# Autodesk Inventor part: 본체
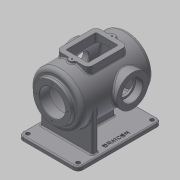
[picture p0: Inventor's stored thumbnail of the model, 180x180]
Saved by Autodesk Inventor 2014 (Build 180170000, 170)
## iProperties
Created: 2016-02
Part Number: 본체
Material: 일반
Document SubType Name: Modeling
Designer: mduedu
Density: 2.71 g/cm^3
Appearance: 기본값
Author: mduedu
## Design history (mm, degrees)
sketch "스케치2"
  geometry: L1 (0, 90)-(0, -90); L2 (65, -90)-(65, 90); L3 (65, 90)-(0, 90); L4 (65, -90)-(0, -90); 2 further points
  constraints: 8 end point, 2 horizontal, 1 coincident, 1 midpoint, 1 parallel, 1 vertical
  dimensions: "d3" = 180 distance of L1.start L1.end; "d5" = 130 diameter of L2 L1
revolve "회전1" sketch "스케치2" stored, may be unused: angle "d7" = 90 deg
sketch "스케치3"
  geometry: C1 r 47.5 at (0, 0); 1 further point
  constraints: 1 centre point, 1 coincident
  dimensions: "d8" = 95 diameter of C1
extrude "돌출2" join sketch "스케치3" distance "d10" = 10; taper "d11" = 0 deg
sketch "스케치5"
  geometry: L1 (47.5, 100)-(47.5, 90) reference; L2 (47.5, 90)-(65, 90) reference; L3 (65, 90)-(65, -90) reference; L4 (-65, -90)-(-65, 90) reference; L5 (-65, 90)-(-47.5, 90) reference; L6 (-47.5, 90)-(-47.5, 100) reference; L7 (-47.5, 100)-(47.5, 100) reference; L8 (55, 75)-(55, -75); L9 (0, 75)-(55, 75); L10 (0, 75)-(0, -75); L11 (65, -90)-(-65, -90) reference; L12 (55, -75)-(0, -75); 1 further point
  constraints: 9 end point, 2 parallel, 2 perpendicular, 1 midpoint, 1 vertical
  dimensions: "d13" = 10 distance between parallel lines of L3 L8; "d15" = 15 distance between parallel lines of L9 L2; "d203" = 15 distance between parallel lines of L11 L12
revolve "회전2" sketch "스케치5" stored, may be unused: angle "d16" = 90 deg
hole "구멍1" diameter "d19" = 65; stored, may be unused: countersink angle "d23" = 90 deg, drill point angle "d25" = 118 deg; dims "d17" = 10, "d18" = 10, "d20" = 6, "d21" = 4, "d22" = 2, "d24" = 8
node "작업 평면1"
sketch "스케치6"
  geometry: L1 (47.5, 100)-(-47.5, 100) reference; C1 r 40 at (0, -27); 1 further point
  constraints: 1 centre point, 1 vertical alignment
  dimensions: "d27" = 80 diameter of C1; "d29" = 127 distance from line of C1.centre L1
extrude "돌출3" join sketch "스케치6" stored distance "d30" = 10; taper "d31" = 0 deg
hole "구멍2" diameter "d34" = 42; stored, may be unused: countersink angle "d38" = 90 deg, drill point angle "d40" = 118 deg; dims "d32" = 10, "d33" = 10, "d35" = 6, "d36" = 52, "d37" = 18, "d39" = 8
sketch "스케치7" dims "d41" = 65
  geometry: C1 r 40 at (0, 0) reference; 3 further points
  constraints: 2 vertical alignment, 1 coincident, 2 other
hole "구멍3" sketch "스케치7" at (0, 32.5) diameter "d43" = 3.242; stored, may be unused: countersink angle "d47" = 90 deg, drill point angle "d49" = 118 deg; dims "d44" = 11, "d45" = 13, "d46" = 18, "d48" = 13
sketch "스케치8" dims "d53" = 80
  geometry: 3 further points
  constraints: 2 vertical alignment, 1 coincident, 2 other
hole "구멍4" sketch "스케치8" at (0, 40) diameter "d56" = 3.242; stored, may be unused: countersink angle "d60" = 90 deg, drill point angle "d62" = 118 deg; dims "d57" = 11, "d58" = 13, "d59" = 18, "d61" = 13
fillet "모깎기1" dims "d66" = 10
fillet "모깎기2" dims "d67" = 3
fillet "모깎기3" dims "d68" = 0.3
chamfer "모따기1" distance "d69" = 1; stored, may be unused: second distance "d70" = 2, angle "d71" = 45 deg
node "작업 평면5"
sketch "스케치10"
  geometry: L1 (-50, 0)-(50, 0); L2 (-65, 64)-(65, 64); L3 (65, 64)-(65, 50); L4 (65, 50)-(-65, 50); L5 (-65, 50)-(-65, 64); 3 further points
  constraints: 10 end point, 2 horizontal, 2 midpoint, 2 vertical, 1 coincident, 1 vertical alignment
  dimensions: "d132" = 100 distance of L1.start L1.end; "d158" = 50 distance between parallel lines of L4 L1; "d159" = 14 distance of L2.end L3.end; "d160" = 130 distance of L2.start L2.end
extrude "돌출5" join sketch "스케치10" stored distance "d84" = 10; taper "d85" = 0 deg
sketch "스케치11"
  geometry: L1 (-100, 64)-(-100, 50) reference; L2 (-100, 50)-(-100, -50); L3 (-65, 80)-(-65, -80) reference; L4 (-100, -50)-(-65, -50); L5 (-100, 50)-(0, 50) reference; 1 further point
  constraints: 4 end point, 1 collinear, 1 perpendicular, 1 point on line
  dimensions: "d161" = 100 distance between parallel lines of L4 L5
feature "리브1" sketch "스케치11" dims "d88" = 1, "d89" = 14, "d90" = 0, "d91" = 0, "d92" = 1, "d93" = 1
fillet "모깎기5" dims "d103" = 3
fillet "모깎기6" dims "d177" = 3
node "작업 평면6"
sketch "스케치15"
  geometry: L1 (-40, 50)-(40, 50); L2 (40, 50)-(40, -50); L3 (40, -50)-(-40, -50); L4 (-40, -50)-(-40, 50); C1 r 7.5 at (0, 50); C2 r 7.5 at (0, -50); 3 further points
  constraints: 8 end point, 2 centre point, 2 coincident, 2 midpoint, 2 parallel, 1 horizontal, 1 perpendicular, 1 vertical alignment
  dimensions: "d110" = 80 distance of L2.end L3.end; "d112" = 50 distance from line of L3 point (0, 0); "d113" = 100 distance of L1.end L2.end; "d149" = 40 distance from line of L4 point (0, 0); "d191" = 15 diameter of C1; "d192" = 15 diameter of C2
extrude "돌출8" join sketch "스케치15" stored distance "d114" = 10; taper "d115" = 0 deg
fillet "모깎기7" dims "d116" = 12, "d193" = 3
sketch "스케치16"
  geometry: L1 (-28, 50)-(-10.062, 50) reference; L2 (28, -50)-(10.062, -50) reference; L3 (40, 38)-(40, -38) reference; L4 (-40, -38)-(-40, 38) reference; L5 (-10.062, -50)-(-28, -50) reference; L6 (10.062, 50)-(28, 50) reference; L7 (-28, -38)-(28, -38); L8 (28, -38)-(28, 38); L9 (28, 38)-(-28, 38); L10 (-28, 38)-(-28, -38); L11 (-28, -38)-(28, 38); L12 (28, -38)-(-28, 38); A1 r 12 centre (28, 38) between (40, 38) and (28, 50) reference; A2 r 12 centre (28, -38) between (28, -50) and (40, -38) reference; A3 r 12 centre (-28, -38) between (-40, -38) and (-28, -50) reference; A4 r 12 centre (-28, 38) between (-28, 50) and (-40, 38) reference; A5 r 3 centre (10.062, -53) between (10.062, -50) and (7.187, -52.143) reference; A6 r 7.5 centre (0, -50) between (-7.187, -52.143) and (7.187, -52.143) reference; A7 r 3 centre (-10.062, -53) between (-7.187, -52.143) and (-10.062, -50) reference; A8 r 3 centre (-10.062, 53) between (-10.062, 50) and (-7.187, 52.143) reference; A9 r 7.5 centre (0, 50) between (7.187, 52.143) and (-7.187, 52.143) reference; A10 r 3 centre (10.062, 53) between (7.187, 52.143) and (10.062, 50) reference; 1 further point
  constraints: 12 end point, 2 midpoint, 2 parallel, 1 horizontal, 1 perpendicular
  dimensions: "d180" = 100 distance between parallel lines of L2 L1 (derived); "d181" = 80 distance between parallel lines of L3 L4 (derived); "d194" = 12 distance between parallel lines of L9 L6; "d195" = 12 distance between parallel lines of L3 L8
extrude "돌출9" cut sketch "스케치16" stored distance "d118" = 10; taper "d119" = 0 deg
fillet "모깎기15" dims "d183" = 3
fillet "모깎기8" dims "d120" = 3
sketch "스케치24"
  geometry: L1 (28, 35)-(28, -35) reference; L2 (25, -38)-(-25, -38) reference; L3 (-28, -35)-(-28, 35) reference; L4 (-25, 38)-(25, 38) reference; L5 (40, 38)-(40, -38) reference; L6 (10.062, 50)-(28, 50) reference; L7 (-28, 50)-(-10.062, 50) reference; L8 (-40, -38)-(-40, 38) reference; L9 (-10.062, -50)-(-28, -50) reference; L10 (28, -50)-(10.062, -50) reference; A1 r 3 centre (25, -35) between (25, -38) and (28, -35) reference; A2 r 3 centre (-25, -35) between (-28, -35) and (-25, -38) reference; A3 r 3 centre (-25, 35) between (-25, 38) and (-28, 35) reference; A4 r 3 centre (25, 35) between (28, 35) and (25, 38) reference; A5 r 12 centre (28, -38) between (28, -50) and (40, -38) reference; A6 r 12 centre (28, 38) between (40, 38) and (28, 50) reference; A7 r 3 centre (10.062, 53) between (7.187, 52.143) and (10.062, 50) reference; A8 r 7.5 centre (0, 50) between (7.187, 52.143) and (-7.187, 52.143) reference; A9 r 3 centre (-10.062, 53) between (-10.062, 50) and (-7.187, 52.143) reference; A10 r 12 centre (-28, 38) between (-28, 50) and (-40, 38) reference; A11 r 12 centre (-28, -38) between (-40, -38) and (-28, -50) reference; A12 r 3 centre (-10.062, -53) between (-7.187, -52.143) and (-10.062, -50) reference; A13 r 7.5 centre (0, -50) between (-7.187, -52.143) and (7.187, -52.143) reference; A14 r 3 centre (10.062, -53) between (10.062, -50) and (7.187, -52.143) reference; 3 further points
  constraints: 2 coincident
hole "구멍7" sketch "스케치24" at (0, 50), (0, -50) diameter "d196" = 3.242; stored, may be unused: countersink angle "d200" = 90 deg, drill point angle "d202" = 118 deg; dims "d197" = 9, "d198" = 4, "d199" = 2, "d201" = 11
sketch "스케치20"
  geometry: L1 (-75, 110)-(75, 110); L2 (75, 110)-(75, -100); L3 (75, -100)-(-75, -100); L4 (-75, -100)-(-75, 110); 2 further points
  constraints: 8 end point, 2 parallel, 1 horizontal, 1 midpoint, 1 perpendicular, 1 vertical alignment
  dimensions: "d162" = 150 distance of L1.start L1.end; "d164" = 210 distance of L1.end L2.end; "d165" = 110 distance from line of L1 point (0, 0)
extrude "돌출12" join sketch "스케치20" distance "d166" = 10; taper "d167" = 0 deg
fillet "모깎기12" dims "d168" = 12
fillet "모깎기13" dims "d169" = 3
fillet "모깎기14" dims "d170" = 3
sketch "스케치21"
  geometry: C1 r 5 at (-63, -98); C2 r 5 at (63, -98); C3 r 5 at (63, 88); C4 r 5 at (-63, 88); A1 r 12 centre (-63, -98) between (-75, -98) and (-63, -110) reference; A2 r 12 centre (-63, 88) between (-63, 100) and (-75, 88) reference; A3 r 12 centre (63, 88) between (75, 88) and (63, 100) reference; A4 r 12 centre (63, -98) between (63, -110) and (75, -98) reference; 1 further point
  constraints: 4 centre point, 4 coincident, 3 equal radius
  dimensions: "d171" = 10 diameter of C1
extrude "돌출13" cut sketch "스케치21" stored distance "d172" = 10; taper "d173" = 0 deg
sketch "스케치22"
  geometry: L1 (75, -98)-(75, 88) reference; 2 further points
  constraints: 1 horizontal alignment, 1 other
  dimensions: "d174" = 15 distance from line of L1 point (60, 0)
feature "엠보싱2" sketch "스케치22" dims "d3" = 180, "d5" = 130, "d16" = 90 deg, "d175" = 0.5, "d176" = 0
node "솔리드2"
pattern_circular "원형 패턴1" dims angle "d51" = 360 deg
mirror "대칭1"
pattern_circular "원형 패턴2" dims angle "d64" = 360 deg
node "투영된 루프3"
node "절단 모서리 투영1"
node "절단 모서리 투영2"
other parameters: "d26" = 75
